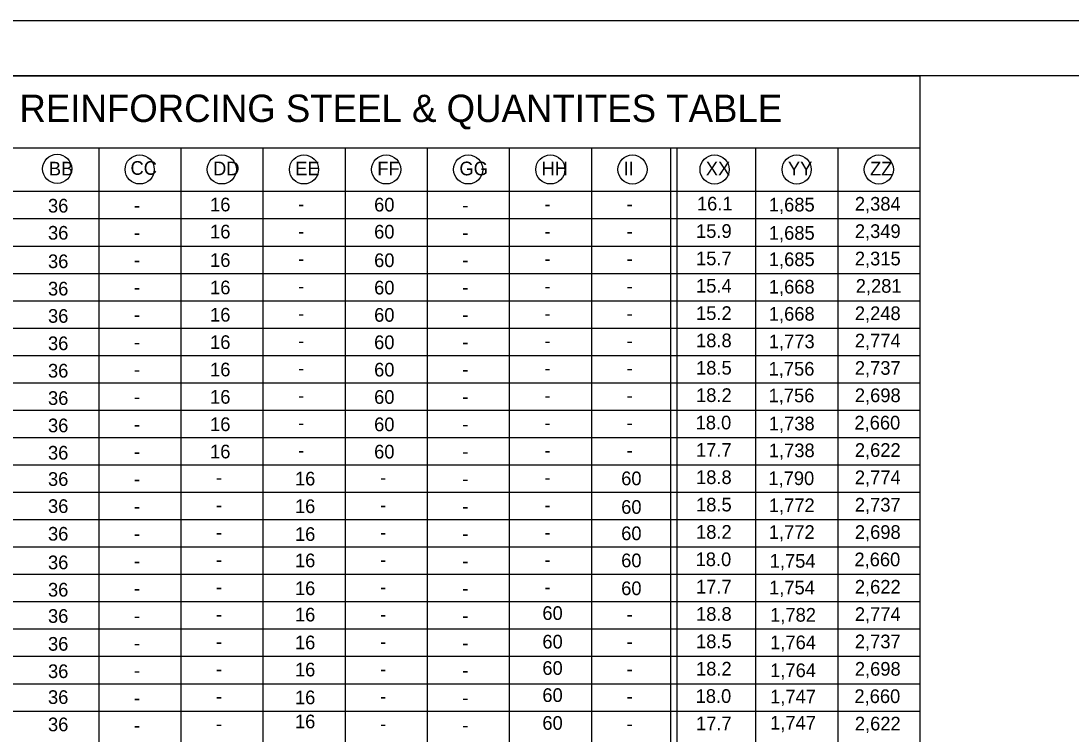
# Model space of a CAD drawing. Extents: x -50.5 to -14.4, y -5.1 to 16.9.
# Drawn here: x -45.7 to -36.11, y 10.42 to 16.93 of the extents above; entities that cross this region are included whole.
import ezdxf

# ---------------------------------------------------------------- set-up
doc = ezdxf.new("R2010")
doc.units = 0
for name, color, linetype in [('BR_AUTO DIMENSION', 7, 'Continuous'), ('BR_BORDER LINES', 7, 'Continuous'), ('BR_TABLE LINES', 7, 'Continuous'), ('BR_TEXT', 7, 'Continuous'), ('Level 31', 7, 'Continuous')]:
    doc.layers.add(name, color=color, linetype=linetype)

msp = doc.modelspace()

# ---------------------------------------------------------------- linework, layer by layer
at = {"layer": 'BR_AUTO DIMENSION'}
for centre in [(-45.3738, 15.5827), (-44.6195, 15.5779), (-43.8693, 15.5779), (-43.1193, 15.5779), (-42.3693, 15.5779), (-41.6193, 15.5779), (-40.8693, 15.5779), (-40.1193, 15.5772), (-39.3693, 15.5772), (-38.6193, 15.5772), (-37.8693, 15.5772)]:
    msp.add_circle(centre, 0.1331, dxfattribs=at)
at = {"layer": 'BR_BORDER LINES'}
for p, q in [((-48.6853, 16.4338), (-37.4943, 16.4338)), ((-15.0192, 16.4338), (-48.6853, 16.4338)), ((-37.4943, 16.4338), (-37.4943, 4.1202))]:
    msp.add_line(p, q, dxfattribs=at)
at = {"layer": 'BR_TABLE LINES'}
for p, q in [((-48.6853, 15.7748), (-37.4943, 15.7748)), ((-44.9943, 15.7748), (-44.9943, 4.1202)), ((-44.2443, 15.7748), (-44.2443, 4.1202)), ((-43.4943, 15.7748), (-43.4943, 4.1202)), ((-42.7443, 15.7748), (-42.7443, 4.1202)), ((-41.9943, 15.7748), (-41.9943, 4.1202)), ((-41.2443, 15.7748), (-41.2443, 4.1202)), ((-40.4943, 15.7748), (-40.4943, 4.1202)), ((-39.7733, 15.7748), (-39.7733, 4.1202)), ((-39.7152, 15.7748), (-39.7152, 4.1202)), ((-38.9943, 15.7748), (-38.9943, 4.1202)), ((-38.2443, 15.7748), (-38.2443, 4.1202)), ((-48.6853, 15.3783), (-37.4943, 15.3783)), ((-47.233, 15.1283), (-37.4943, 15.1283)), ((-47.233, 14.8783), (-37.4943, 14.8783)), ((-47.233, 14.6283), (-37.4943, 14.6283)), ((-47.233, 14.3783), (-37.4943, 14.3783)), ((-48.0649, 14.1289), (-37.4943, 14.1289)), ((-47.233, 13.8789), (-37.4943, 13.8789)), ((-47.233, 13.6289), (-37.4943, 13.6289)), ((-47.233, 13.3789), (-37.4943, 13.3789)), ((-47.233, 13.1289), (-37.4943, 13.1289)), ((-48.0649, 12.8795), (-37.4943, 12.8795)), ((-47.233, 12.6295), (-37.4943, 12.6295)), ((-47.233, 12.3795), (-37.4943, 12.3795)), ((-47.233, 12.1295), (-37.4943, 12.1295)), ((-47.233, 11.8795), (-37.4943, 11.8795)), ((-48.0649, 11.63), (-37.4943, 11.63)), ((-47.233, 11.38), (-37.4943, 11.38)), ((-47.233, 11.13), (-37.4943, 11.13)), ((-47.233, 10.88), (-37.4943, 10.88)), ((-47.233, 10.63), (-37.4943, 10.63))]:
    msp.add_line(p, q, dxfattribs=at)
at = {"layer": 'Level 31'}
msp.add_lwpolyline([(-50.5186, -5.0661), (-14.5186, -5.0661), (-14.5186, 16.9339), (-50.5186, 16.9339)], close=True, dxfattribs=at)

# ---------------------------------------------------------------- texts
at = {"layer": 'BR_TEXT'}
for s, height, p in [('REINFORCING STEEL & QUANTITES TABLE', 0.25, (-45.7177, 16.0112)), ('CC', 0.125, (-44.7036, 15.5286)), ('DD', 0.125, (-43.9496, 15.5239)), ('EE', 0.125, (-43.1996, 15.5239)), ('FF', 0.125, (-42.4496, 15.5239)), ('GG', 0.125, (-41.6996, 15.5239)), ('HH', 0.125, (-40.9496, 15.5239)), ('II', 0.125, (-40.1996, 15.5232)), ('XX', 0.125, (-39.4496, 15.5232)), ('YY', 0.125, (-38.6996, 15.5232)), ('ZZ', 0.125, (-37.9496, 15.5232)), ('36', 0.125, (-45.4572, 15.184)), ('16', 0.125, (-43.977, 15.1949)), ('-', 0.125, (-43.1732, 15.1999)), ('60', 0.125, (-42.4786, 15.1936)), ('-', 0.125, (-40.9232, 15.1999)), ('-', 0.125, (-40.1732, 15.1999)), ('16.1', 0.125, (-39.5303, 15.2027)), ('1,685', 0.125, (-38.8736, 15.1936)), ('2,384', 0.125, (-38.0882, 15.2014)), ('-', 0.125, (-44.6721, 15.1882)), ('-', 0.125, (-41.6736, 15.1891)), ('36', 0.125, (-45.4572, 14.9365)), ('16', 0.125, (-43.977, 14.9474)), ('60', 0.125, (-42.4786, 14.9461)), ('15.9', 0.125, (-39.5386, 14.9527)), ('1,685', 0.125, (-38.8736, 14.9354)), ('2,349', 0.125, (-38.0882, 14.9514)), ('-', 0.125, (-44.6721, 14.9382)), ('-', 0.125, (-43.1732, 14.9499)), ('-', 0.125, (-41.6736, 14.9391)), ('-', 0.125, (-40.9232, 14.9499)), ('-', 0.125, (-40.1732, 14.9499)), ('36', 0.125, (-45.4572, 14.6762)), ('16', 0.125, (-43.977, 14.6872)), ('60', 0.125, (-42.4786, 14.6859)), ('15.7', 0.125, (-39.5386, 14.7027)), ('1,685', 0.125, (-38.8736, 14.6947)), ('2,315', 0.125, (-38.0882, 14.7014)), ('-', 0.125, (-44.6721, 14.6882)), ('-', 0.125, (-43.1732, 14.6999)), ('-', 0.125, (-41.6736, 14.6891)), ('-', 0.125, (-40.9232, 14.6999)), ('-', 0.125, (-40.1732, 14.6999)), ('15.4', 0.125, (-39.5386, 14.4527)), ('2,281', 0.125, (-38.0799, 14.4514)), ('36', 0.125, (-45.4572, 14.4262)), ('-', 0.125, (-44.6721, 14.4382)), ('16', 0.125, (-43.977, 14.4372)), ('-', 0.125, (-43.1732, 14.4499)), ('60', 0.125, (-42.4786, 14.4359)), ('-', 0.125, (-41.6736, 14.4391)), ('-', 0.125, (-40.9232, 14.4499)), ('-', 0.125, (-40.1732, 14.4499)), ('1,668', 0.125, (-38.8736, 14.4437)), ('36', 0.125, (-45.4572, 14.1768)), ('16', 0.125, (-43.977, 14.1877)), ('60', 0.125, (-42.4786, 14.1864)), ('15.2', 0.125, (-39.5386, 14.2027)), ('1,668', 0.125, (-38.8736, 14.1962)), ('2,248', 0.125, (-38.0882, 14.2014)), ('-', 0.125, (-44.6721, 14.1882)), ('-', 0.125, (-43.1732, 14.1999)), ('-', 0.125, (-41.6736, 14.1891)), ('-', 0.125, (-40.9232, 14.1999)), ('-', 0.125, (-40.1732, 14.1999)), ('36', 0.125, (-45.4572, 13.9268)), ('16', 0.125, (-43.977, 13.9377)), ('-', 0.125, (-43.1732, 13.9505)), ('60', 0.125, (-42.4786, 13.9364)), ('-', 0.125, (-40.9232, 13.9505)), ('-', 0.125, (-40.1732, 13.9505)), ('18.8', 0.125, (-39.5386, 13.9532)), ('1,773', 0.125, (-38.8736, 13.9443)), ('2,774', 0.125, (-38.0882, 13.952)), ('-', 0.125, (-44.6721, 13.9382)), ('-', 0.125, (-41.6736, 13.9391)), ('16', 0.125, (-43.977, 13.6877)), ('60', 0.125, (-42.4786, 13.6864)), ('18.5', 0.125, (-39.5386, 13.7032)), ('1,756', 0.125, (-38.876, 13.6943)), ('2,737', 0.125, (-38.0882, 13.702)), ('36', 0.125, (-45.4572, 13.6768)), ('-', 0.125, (-44.6721, 13.6882)), ('-', 0.125, (-43.1732, 13.7005)), ('-', 0.125, (-41.6736, 13.6891)), ('-', 0.125, (-40.9232, 13.7005)), ('-', 0.125, (-40.1732, 13.7005)), ('36', 0.125, (-45.4572, 13.4268)), ('16', 0.125, (-43.977, 13.4377)), ('60', 0.125, (-42.4786, 13.4364)), ('18.2', 0.125, (-39.5386, 13.4532)), ('1,756', 0.125, (-38.876, 13.4507)), ('2,698', 0.125, (-38.0882, 13.452)), ('-', 0.125, (-44.6721, 13.4382)), ('-', 0.125, (-43.1732, 13.4505)), ('-', 0.125, (-41.6736, 13.4391)), ('-', 0.125, (-40.9232, 13.4505)), ('-', 0.125, (-40.1732, 13.4505)), ('18.0', 0.125, (-39.5425, 13.2032)), ('36', 0.125, (-45.4572, 13.1768)), ('-', 0.125, (-44.6721, 13.1882)), ('16', 0.125, (-43.977, 13.1877)), ('-', 0.125, (-43.1732, 13.2005)), ('60', 0.125, (-42.4786, 13.1864)), ('-', 0.125, (-41.6736, 13.1891)), ('-', 0.125, (-40.9232, 13.2005)), ('-', 0.125, (-40.1732, 13.2005)), ('1,738', 0.125, (-38.8736, 13.1943)), ('2,660', 0.125, (-38.0921, 13.202)), ('36', 0.125, (-45.4572, 12.9274)), ('16', 0.125, (-43.977, 12.9383)), ('60', 0.125, (-42.4786, 12.937)), ('17.7', 0.125, (-39.5386, 12.9532)), ('1,738', 0.125, (-38.8736, 12.9488)), ('2,622', 0.125, (-38.0882, 12.952)), ('-', 0.125, (-44.6721, 12.9382)), ('-', 0.125, (-43.1732, 12.9505)), ('-', 0.125, (-41.6736, 12.9391)), ('-', 0.125, (-40.9232, 12.9505)), ('-', 0.125, (-40.1732, 12.9505)), ('36', 0.125, (-45.4572, 12.6871)), ('-', 0.125, (-43.9232, 12.7011)), ('16', 0.125, (-43.2017, 12.6909)), ('-', 0.125, (-42.4232, 12.7011)), ('-', 0.125, (-40.9232, 12.7011)), ('60', 0.125, (-40.2223, 12.693)), ('18.8', 0.125, (-39.5386, 12.7038)), ('1,790', 0.125, (-38.8776, 12.6944)), ('2,774', 0.125, (-38.0882, 12.7025)), ('-', 0.125, (-44.6721, 12.6882)), ('-', 0.125, (-41.6736, 12.6891)), ('36', 0.125, (-45.4572, 12.4396)), ('16', 0.125, (-43.2017, 12.4386)), ('18.5', 0.125, (-39.5386, 12.4538)), ('1,772', 0.125, (-38.8736, 12.4469)), ('2,737', 0.125, (-38.0882, 12.4525)), ('-', 0.125, (-44.6721, 12.4382)), ('-', 0.125, (-43.9232, 12.4511)), ('-', 0.125, (-42.4232, 12.4511)), ('-', 0.125, (-41.6736, 12.4391)), ('-', 0.125, (-40.9232, 12.4511)), ('60', 0.125, (-40.2223, 12.4318)), ('36', 0.125, (-45.4572, 12.1869)), ('16', 0.125, (-43.2017, 12.1842)), ('60', 0.125, (-40.2223, 12.1911)), ('18.2', 0.125, (-39.5386, 12.2038)), ('1,772', 0.125, (-38.8736, 12.2026)), ('2,698', 0.125, (-38.0882, 12.2025)), ('-', 0.125, (-44.6721, 12.1882)), ('-', 0.125, (-43.9232, 12.2011)), ('-', 0.125, (-42.4232, 12.2011)), ('-', 0.125, (-41.6736, 12.1891)), ('-', 0.125, (-40.9232, 12.2011)), ('36', 0.125, (-45.4572, 11.9256)), ('-', 0.125, (-44.6721, 11.9382)), ('-', 0.125, (-43.9232, 11.9511)), ('16', 0.125, (-43.2017, 11.9436)), ('-', 0.125, (-42.4232, 11.9511)), ('-', 0.125, (-41.6736, 11.9391)), ('-', 0.125, (-40.9232, 11.9511)), ('60', 0.125, (-40.2223, 11.9436)), ('18.0', 0.125, (-39.5425, 11.9538)), ('1,754', 0.125, (-38.8658, 11.9394)), ('2,660', 0.125, (-38.0921, 11.9525)), ('36', 0.125, (-45.4572, 11.6761)), ('16', 0.125, (-43.2017, 11.6892)), ('60', 0.125, (-40.2223, 11.6892)), ('17.7', 0.125, (-39.5386, 11.7038)), ('1,754', 0.125, (-38.8716, 11.6958)), ('2,622', 0.125, (-38.0882, 11.7025)), ('-', 0.125, (-44.6721, 11.6882)), ('-', 0.125, (-43.9232, 11.7011)), ('-', 0.125, (-42.4232, 11.7011)), ('-', 0.125, (-41.6736, 11.6891)), ('-', 0.125, (-40.9232, 11.7011)), ('36', 0.125, (-45.4572, 11.4358)), ('16', 0.125, (-43.2017, 11.4486)), ('60', 0.125, (-40.9421, 11.4624)), ('18.8', 0.125, (-39.5386, 11.4544)), ('1,782', 0.125, (-38.8618, 11.4464)), ('2,774', 0.125, (-38.0882, 11.4531)), ('-', 0.125, (-44.6721, 11.4382)), ('-', 0.125, (-43.9232, 11.4517)), ('-', 0.125, (-42.4232, 11.4517)), ('-', 0.125, (-41.6736, 11.4391)), ('-', 0.125, (-40.1732, 11.4517)), ('16', 0.125, (-43.2017, 11.1942)), ('60', 0.125, (-40.9421, 11.2011)), ('18.5', 0.125, (-39.5386, 11.2044)), ('1,764', 0.125, (-38.8618, 11.1949)), ('2,737', 0.125, (-38.0882, 11.2031)), ('36', 0.125, (-45.4572, 11.1812)), ('-', 0.125, (-44.6721, 11.1882)), ('-', 0.125, (-43.9232, 11.2017)), ('-', 0.125, (-42.4232, 11.2017)), ('-', 0.125, (-41.6736, 11.1891)), ('-', 0.125, (-40.1732, 11.2017)), ('36', 0.125, (-45.4572, 10.9312)), ('16', 0.125, (-43.2017, 10.9467)), ('60', 0.125, (-40.9421, 10.9605)), ('18.2', 0.125, (-39.5386, 10.9544)), ('1,764', 0.125, (-38.8618, 10.9396)), ('2,698', 0.125, (-38.0882, 10.9531)), ('-', 0.125, (-44.6721, 10.9382)), ('-', 0.125, (-43.9232, 10.9517)), ('-', 0.125, (-42.4232, 10.9517)), ('-', 0.125, (-41.6736, 10.9391)), ('-', 0.125, (-40.1732, 10.9517)), ('60', 0.125, (-40.9421, 10.713)), ('36', 0.125, (-45.4572, 10.6949)), ('-', 0.125, (-44.6721, 10.6882)), ('-', 0.125, (-43.9232, 10.7017)), ('16', 0.125, (-43.2017, 10.6923)), ('-', 0.125, (-42.4232, 10.7017)), ('-', 0.125, (-41.6736, 10.6891)), ('-', 0.125, (-40.1732, 10.7017)), ('18.0', 0.125, (-39.5425, 10.7044)), ('1,747', 0.125, (-38.8618, 10.6999)), ('2,660', 0.125, (-38.0921, 10.7031)), ('36', 0.125, (-45.4572, 10.4455)), ('16', 0.125, (-43.2017, 10.4723)), ('60', 0.125, (-40.9421, 10.4586)), ('17.7', 0.125, (-39.5386, 10.4544)), ('1,747', 0.125, (-38.8618, 10.4603)), ('2,622', 0.125, (-38.0882, 10.4531)), ('-', 0.125, (-44.6721, 10.4382)), ('-', 0.125, (-43.9232, 10.4517)), ('-', 0.125, (-42.4232, 10.4517)), ('-', 0.125, (-41.6736, 10.4391)), ('-', 0.125, (-40.1732, 10.4517))]:
    msp.add_text(s, height=height, dxfattribs=at).set_placement(p)
msp.add_text('BB', height=0.125, rotation=360, dxfattribs=at).set_placement((-45.4496, 15.5227))

doc.saveas('drawing.dxf')
